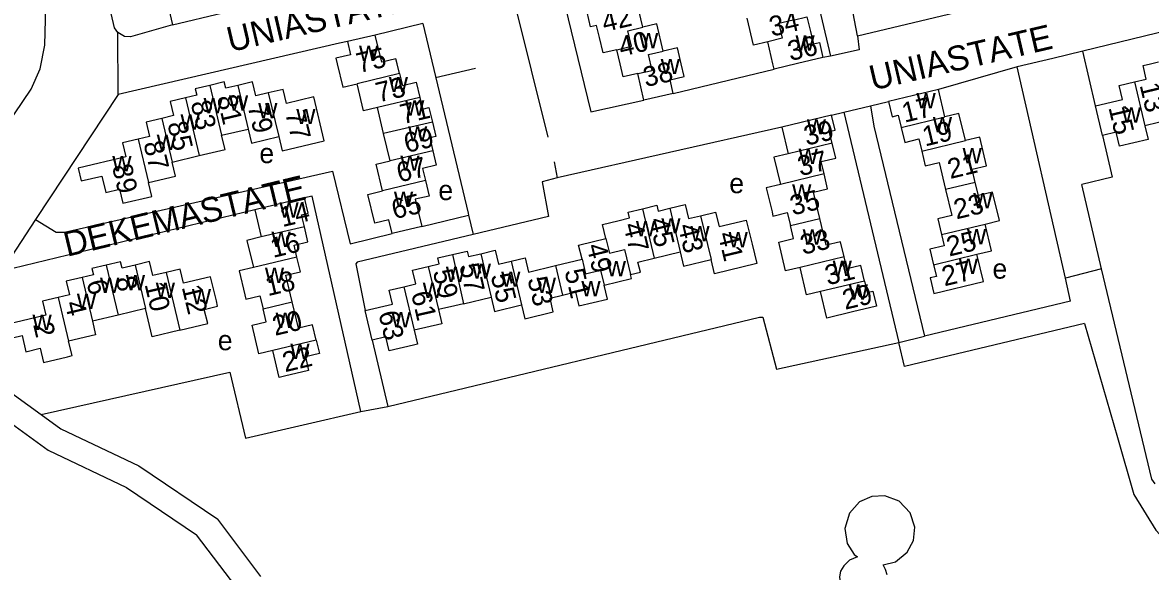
# Model space of a CAD drawing. Extents: x 157646 to 159241, y 379213 to 381217.
# Drawn here: x 158413 to 158640, y 380397.8 to 380508.3 of the extents above; entities that cross this region are included whole.
import ezdxf

# ---------------------------------------------------------------- set-up
doc = ezdxf.new("R2010")
doc.units = 0
for name, color, linetype in [('BLT_Basislijn', 7, 'Continuous'), ('BLT_Bebouwing', 7, 'Continuous'), ('BLT_Centroide', 7, 'Continuous'), ('BLT_Huisnummer', 7, 'Continuous'), ('BLT_Huisnummer_ tussenligend', 7, 'Continuous'), ('BLT_Onderverdeling_panden', 7, 'Continuous'), ('BLT_Straatnaam', 7, 'Continuous'), ('BLT_Vlakafsluiter', 7, 'Continuous')]:
    doc.layers.add(name, color=color, linetype=linetype)

msp = doc.modelspace()

# ---------------------------------------------------------------- linework, layer by layer
at = {"layer": 'BLT_Basislijn'}
for p, q in [((158581.07, 380505.63), (158578.69, 380518.3)), ((158493.56, 380508.08), (158483.99, 380505.77)), ((158626.43, 380502.53), (158620.37, 380501.06)), ((158629, 380491.49), (158626.43, 380502.53)), ((158575.65, 380501.55), (158574.12, 380501.22)), ((158620.37, 380501.06), (158613.19, 380499.36)), ((158504.16, 380499.04), (158496.14, 380497.15)), ((158543.97, 380494.03), (158564.31, 380498.87)), ((158613.19, 380499.36), (158597.35, 380494.78)), ((158622.92, 380456.82), (158613.19, 380499.36)), ((158578.33, 380490.24), (158583.67, 380491.51)), ((158583.67, 380491.51), (158587.29, 380492.37)), ((158575.86, 380489.66), (158578.33, 380490.24)), ((158578.33, 380490.24), (158589.42, 380443.84)), ((158565.83, 380487.25), (158520.61, 380477.03)), ((158519.99, 380480.22), (158520.61, 380477.03)), ((158630.17, 380458.72), (158626.25, 380475.68)), ((158459.75, 380470.6), (158408.83, 380458.22)), ((158415.6, 380468.65), (158408.83, 380458.22)), ((158493.33, 380467.25), (158502.78, 380469.5)), ((158502.78, 380469.5), (158503.69, 380465.58)), ((158630.17, 380458.72), (158622.92, 380456.82)), ((158623.96, 380452.17), (158594.59, 380445.15)), ((158483.39, 380444.35), (158486.52, 380431)), ((158589.42, 380443.84), (158594.59, 380445.15)), ((158407.74, 380435.87), (158416.7, 380429.36)), ((158481.1, 380429.98), (158486.52, 380431)), ((158460.93, 380396.74), (158452.27, 380408.29))]:
    msp.add_line(p, q, dxfattribs=at)
for points in [[(158382, 380486.03), (158394.7, 380478.15), (158397.65, 380476.58), (158401, 380475.76), (158402.65, 380477.1), (158414.74, 380494.85), (158416.53, 380498.98), (158417.47, 380503.76), (158417.68, 380511.48), (158409.95, 380583.17)], [(158432.15, 380506.31), (158431.46, 380507.21), (158430.83, 380510.09), (158424.78, 380563.88), (158424.7, 380564.63)], [(158581.93, 380543.49), (158581, 380543.28), (158567.24, 380539.99), (158567, 380538.29), (158575.65, 380501.55)], [(158504.69, 380526.29), (158505.57, 380522.37), (158518.89, 380525.34), (158527.39, 380490.29), (158538.07, 380492.65)], [(158581.07, 380505.63), (158618.83, 380514.67), (158619.9, 380514.93)], [(158691.66, 380491.57), (158680.6, 380511.16), (158678.79, 380513.56), (158677.11, 380514.16), (158675.83, 380514.19), (158665.87, 380512.12), (158626.43, 380502.53)], [(158505.34, 380511.18), (158511.1, 380512.31), (158512.05, 380512.19), (158518.7, 380485.21)], [(158443.18, 380507.82), (158434.73, 380505.44), (158433.52, 380505.48), (158432.15, 380506.31)], [(158493.56, 380508.08), (158502.68, 380469.93), (158502.78, 380469.5)], [(158478.38, 380504.44), (158476.81, 380504.14), (158432.24, 380493.79)], [(158581.07, 380505.63), (158581.39, 380502.81), (158575.65, 380501.55)], [(158432.24, 380493.79), (158415.6, 380468.65)], [(158583.67, 380491.51), (158584.39, 380487.45), (158594.59, 380445.15)], [(158630.41, 380485.56), (158632.37, 380477.18), (158626.25, 380475.68)], [(158415.6, 380468.65), (158419.74, 380466.05), (158421.43, 380466.05), (158475.39, 380478.34), (158478.91, 380463.75), (158487.39, 380465.84)], [(158520.61, 380477.03), (158517.59, 380476.23), (158518.87, 380469.24), (158503.69, 380465.58)], [(158481.1, 380429.98), (158471.3, 380473.31), (158469.72, 380472.97)], [(158503.69, 380465.58), (158480.37, 380460.04), (158480.05, 380459.72), (158481.98, 380450.28)], [(158623.96, 380452.17), (158622.92, 380456.82)], [(158640.99, 380415.42), (158640.35, 380416.32), (158630.17, 380458.72)], [(158486.52, 380431), (158561.35, 380448.95), (158562.04, 380449), (158564.77, 380438.53), (158589.42, 380443.84)], [(158626.79, 380447.71), (158590.56, 380439.04), (158589.42, 380443.84)], [(158626.79, 380447.71), (158633.39, 380424.75)], [(158416.7, 380429.36), (158454.68, 380437.9), (158457.86, 380424.59), (158481.1, 380429.98)], [(158404.8, 380431.83), (158418.11, 380422.16), (158433.89, 380414.67), (158447.97, 380405.16)], [(158416.7, 380429.36), (158420.67, 380426.47), (158436.38, 380419.03), (158452.27, 380408.29)], [(158633.39, 380424.75), (158636.69, 380413.23), (158641.14, 380406.08), (158645.36, 380401.49), (158645.92, 380400.19), (158645.87, 380396.15), (158642.14, 380389.54), (158637.32, 380383.71), (158629.31, 380376.48), (158618.08, 380369), (158616.64, 380365.53)], [(158583.93, 380412.89), (158581.5, 380411.8), (158579.44, 380409.53), (158578.52, 380406.45), (158579, 380403.42), (158580.43, 380401.17), (158581.04, 380400.73), (158579.43, 380400.03), (158578.3, 380398.92), (158577.65, 380397.83), (158577.43, 380396.71), (158577.57, 380395.45), (158577.86, 380394.21), (158578.56, 380393.09)], [(158587.05, 380397.1), (158586.71, 380398.18), (158586.27, 380399.12), (158588.72, 380399.7), (158591.1, 380401.63), (158592.34, 380404), (158592.6, 380406.66), (158591.67, 380409.57), (158589.46, 380411.91), (158586.6, 380413.01), (158583.93, 380412.89)], [(158371.84, 380404.74), (158408.18, 380378.92), (158409.65, 380377.6), (158411.02, 380375.86), (158413.89, 380370.53), (158415.7, 380360.95), (158417.2, 380357.34), (158418.61, 380354.92), (158421.49, 380351.01), (158424.52, 380348.6), (158429.22, 380345.84), (158436.86, 380344.43), (158443.38, 380345.1), (158477.93, 380359), (158481.57, 380360.73), (158481.57, 380361.05), (158447.97, 380405.16)]]:
    msp.add_lwpolyline(points, dxfattribs=at)
at = {"layer": 'BLT_Bebouwing'}
for p, q in [((158537.84, 380507.34), (158536.59, 380512.68)), ((158443.18, 380507.82), (158453.31, 380510.22)), ((158483.99, 380505.77), (158478.38, 380504.44)), ((158543.97, 380494.03), (158538.07, 380492.65)), ((158597.35, 380494.78), (158587.29, 380492.37)), ((158598.67, 380489.3), (158597.35, 380494.78)), ((158485.67, 380485.92), (158484.42, 380491.18)), ((158630.41, 380485.56), (158629, 380491.49)), ((158575.86, 380489.66), (158565.83, 380487.25)), ((158453.06, 380485.59), (158458.38, 380486.85)), ((158565.83, 380487.25), (158567.12, 380481.85)), ((158486.97, 380480.44), (158485.67, 380485.92)), ((158469.72, 380472.97), (158459.75, 380470.6)), ((158459.75, 380470.6), (158461.05, 380465.12)), ((158493.33, 380467.25), (158487.39, 380465.84)), ((158527.94, 380464.21), (158530.42, 380464.8)), ((158540.15, 380460.85), (158545.39, 380462.11)), ((158520.24, 380459.35), (158525.62, 380460.64)), ((158501.77, 380451.66), (158507.33, 380452.99)), ((158437.71, 380450.71), (158432.21, 380449.4)), ((158483.39, 380444.35), (158481.98, 380450.28)), ((158432.21, 380449.4), (158427.04, 380448.17))]:
    msp.add_line(p, q, dxfattribs=at)
for points in [[(158443.06, 380513.69), (158443.63, 380511.29), (158442.41, 380510.99), (158443.18, 380507.82)], [(158529.1, 380505.3), (158528.55, 380507.68), (158527.35, 380507.4), (158526.65, 380510.36)], [(158563, 380504.43), (158560.12, 380503.75), (158558.84, 380509.17)], [(158568.14, 380508.79), (158570.9, 380509.45), (158571.61, 380506.47)], [(158541.93, 380502.51), (158540.65, 380508), (158537.84, 380507.34)], [(158478.38, 380504.44), (158479, 380501.8), (158476.08, 380501.11), (158476.34, 380500), (158477.44, 380495.28), (158480.32, 380495.96)], [(158488.86, 380498.02), (158488.39, 380500), (158488.15, 380501.01), (158485.28, 380500.33), (158483.99, 380505.77)], [(158532.62, 380502.81), (158529.84, 380502.16), (158529.1, 380505.3)], [(158564.31, 380498.87), (158564.04, 380500), (158563, 380504.43)], [(158571.61, 380506.47), (158572.19, 380504.01), (158573.39, 380504.29), (158574.12, 380501.22)], [(158536.82, 380498), (158533.89, 380497.34), (158533.27, 380500), (158532.62, 380502.81)], [(158543.97, 380494.03), (158543.33, 380496.77), (158546.16, 380497.44), (158545.56, 380500), (158545.02, 380502.31), (158544.82, 380503.19), (158541.93, 380502.51)], [(158574.12, 380501.22), (158569.02, 380500.01), (158564.31, 380498.87)], [(158636.81, 380496.33), (158639.21, 380496.9), (158638.56, 380499.64), (158640.03, 380500), (158641.67, 380500.39)], [(158488.86, 380498.02), (158489.44, 380495.62), (158492.22, 380496.28), (158492.95, 380493.21)], [(158538.07, 380492.65), (158536.82, 380498)], [(158450.67, 380495.63), (158447.75, 380494.94), (158448.06, 380493.65), (158445.77, 380493.11)], [(158456.29, 380495.62), (158453.9, 380495.05), (158453.59, 380496.33), (158450.67, 380495.63)], [(158462.46, 380494.14), (158459.96, 380493.55), (158459.3, 380496.33), (158456.29, 380495.62)], [(158484.42, 380491.18), (158481.62, 380490.52), (158480.32, 380495.96)], [(158629, 380491.49), (158634.4, 380492.78), (158633.73, 380495.59), (158636.81, 380496.33)], [(158445.77, 380493.11), (158442.67, 380492.37), (158443.34, 380489.55), (158441.02, 380488.99)], [(158464.56, 380485.34), (158465.24, 380482.49), (158473.72, 380484.5), (158471.62, 380493.34), (158466.09, 380492.02), (158465.42, 380494.84), (158462.46, 380494.14)], [(158492.95, 380493.21), (158493.51, 380490.86), (158494.8, 380491.17), (158495.49, 380488.26)], [(158587.29, 380492.37), (158588.02, 380489.3), (158589.28, 380489.61), (158589.86, 380487.19)], [(158643.74, 380491.66), (158644.42, 380488.83), (158638.91, 380487.52)], [(158441.02, 380488.99), (158437.85, 380488.24), (158438.54, 380485.35), (158436.24, 380484.8)], [(158575.97, 380483.97), (158575.39, 380486.37), (158576.58, 380486.65), (158575.86, 380489.66)], [(158602.79, 380484.53), (158601.48, 380489.98), (158598.67, 380489.3)], [(158458.38, 380486.85), (158459.05, 380484.03), (158464.56, 380485.34)], [(158495.49, 380488.26), (158496.18, 380485.35), (158494.96, 380485.06), (158495.57, 380482.49)], [(158589.86, 380487.19), (158590.59, 380484.17), (158593.41, 380484.85), (158593.99, 380482.42)], [(158638.91, 380487.52), (158639.57, 380484.75), (158633.8, 380483.38), (158633.12, 380486.21), (158630.41, 380485.56)], [(158436.24, 380484.8), (158433.11, 380484.06), (158433.77, 380481.27), (158424.18, 380478.99), (158424.8, 380476.4), (158428.94, 380477.38), (158429.73, 380474.07), (158432.52, 380474.73), (158433.19, 380471.9), (158438.98, 380473.28), (158438.31, 380476.09)], [(158448.53, 380481.49), (158453.74, 380482.73), (158453.06, 380485.59)], [(158604.78, 380476.11), (158604.15, 380478.74), (158607.06, 380479.44), (158605.67, 380485.23), (158602.79, 380484.53)], [(158495.57, 380482.49), (158496.27, 380479.56), (158493.5, 380478.91), (158494.09, 380476.46)], [(158567.12, 380481.85), (158564.25, 380481.16), (158565.56, 380475.71)], [(158574.35, 380477.81), (158573.76, 380480.28), (158576.68, 380480.99), (158575.97, 380483.97)], [(158593.99, 380482.42), (158594.71, 380479.41), (158597.5, 380480.08), (158598.8, 380474.67)], [(158438.31, 380476.09), (158443.77, 380477.39), (158443.11, 380480.2)], [(158443.11, 380480.2), (158448.53, 380481.49)], [(158485.43, 380474.4), (158484.15, 380479.77), (158486.97, 380480.44)], [(158573.48, 380468.83), (158572.2, 380474.14), (158575.06, 380474.82), (158574.35, 380477.81)], [(158494.09, 380476.46), (158494.82, 380473.36), (158492.03, 380472.7), (158493.33, 380467.25)], [(158565.56, 380475.71), (158562.7, 380475.02), (158563.87, 380470.16), (158564.06, 380469.33), (158566.93, 380470.02), (158567.55, 380467.41)], [(158606.77, 380467.72), (158609.63, 380468.41), (158608.25, 380474.16), (158605.41, 380473.48), (158604.78, 380476.11)], [(158469.72, 380467.19), (158469.15, 380469.6), (158470.45, 380469.91), (158469.72, 380472.97)], [(158487.39, 380465.84), (158486.74, 380468.59), (158483.87, 380467.9), (158482.49, 380473.7), (158485.43, 380474.4)], [(158598.8, 380474.67), (158600.06, 380469.41), (158597.25, 380468.74), (158598, 380465.62)], [(158532.79, 380468.38), (158535.15, 380468.95), (158534.87, 380470.11), (158537.76, 380470.81)], [(158537.76, 380470.81), (158540.65, 380471.5), (158540.93, 380470.33), (158543.28, 380470.89)], [(158543.28, 380470.89), (158546.41, 380471.64), (158547.08, 380468.83), (158549.46, 380469.4)], [(158530.42, 380464.8), (158529.74, 380467.65), (158532.79, 380468.38)], [(158549.46, 380469.4), (158552.51, 380470.13), (158553.21, 380467.21), (158558.69, 380468.52), (158559.85, 380463.66), (158560.79, 380459.76), (158552.27, 380457.72), (158551.58, 380460.59)], [(158578.36, 380461.09), (158577.63, 380464.13), (158574.77, 380463.44), (158573.48, 380468.83)], [(158468.22, 380461.08), (158467.65, 380463.48), (158470.44, 380464.14), (158469.72, 380467.19)], [(158569.51, 380458.97), (158566.61, 380458.28), (158565.21, 380464.09), (158568.18, 380464.81), (158567.55, 380467.41)], [(158605.12, 380461.63), (158608.06, 380462.33), (158606.77, 380467.72)], [(158461.05, 380465.12), (158458.15, 380464.43), (158459.45, 380459)], [(158525.62, 380460.64), (158524.93, 380463.49), (158527.94, 380464.21)], [(158598, 380465.62), (158598.55, 380463.34), (158595.64, 380462.64), (158596.38, 380459.53)], [(158494.64, 380459.17), (158496.85, 380459.69), (158496.56, 380460.93), (158499.52, 380461.6)], [(158499.52, 380461.6), (158502.49, 380462.27), (158502.76, 380461.15), (158505.23, 380461.74)], [(158505.23, 380461.74), (158508.12, 380462.43), (158508.8, 380459.62), (158511.35, 380460.23)], [(158545.39, 380462.11), (158546.07, 380459.27), (158551.58, 380460.59)], [(158596.38, 380459.53), (158596.95, 380457.16), (158595.68, 380456.86), (158596.42, 380453.76), (158606.43, 380456.16), (158605.12, 380461.63)], [(158429.83, 380459.42), (158426.94, 380458.74), (158427.23, 380457.5), (158424.95, 380456.96)], [(158435.63, 380459.45), (158433.02, 380458.83), (158432.72, 380460.11), (158429.83, 380459.42)], [(158441.87, 380457.99), (158439.23, 380457.36), (158438.57, 380460.15), (158435.63, 380459.45)], [(158467.28, 380452.04), (158466.01, 380457.4), (158468.93, 380458.1), (158468.22, 380461.08)], [(158489.75, 380455.1), (158492.14, 380455.67), (158491.48, 380458.42), (158494.64, 380459.17)], [(158511.35, 380460.23), (158514.18, 380460.91), (158514.86, 380458.06), (158520.24, 380459.35)], [(158535.38, 380457.54), (158537.38, 380458.02), (158536.88, 380460.07), (158540.15, 380460.85)], [(158582.48, 380456.24), (158581.73, 380459.37), (158578.93, 380458.7), (158578.36, 380461.09)], [(158424.95, 380456.96), (158421.77, 380456.2), (158422.43, 380453.46), (158420.16, 380452.92)], [(158444.63, 380446.37), (158450.25, 380447.71), (158449.57, 380450.54), (158452.25, 380451.18), (158452, 380452.24), (158450.84, 380457.11), (158445.38, 380455.81), (158444.7, 380458.66), (158441.87, 380457.99)], [(158459.45, 380459), (158456.58, 380458.32), (158457.74, 380453.45), (158457.94, 380452.6), (158460.78, 380453.27), (158461.41, 380450.65)], [(158530.04, 380455.43), (158535.57, 380456.76), (158535.38, 380457.54)], [(158573.63, 380454.12), (158570.83, 380453.45), (158569.51, 380458.97)], [(158481.98, 380450.28), (158487.46, 380451.59), (158486.79, 380454.4), (158489.75, 380455.1)], [(158521.66, 380453.41), (158524.31, 380454.05), (158524.99, 380451.23), (158530.72, 380452.61), (158530.04, 380455.43)], [(158582.48, 380456.24), (158583.03, 380453.95), (158584.18, 380454.23), (158584.91, 380451.18), (158580.05, 380450.02), (158574.91, 380448.78), (158573.63, 380454.12)], [(158420.16, 380452.92), (158416.98, 380452.16), (158417.65, 380449.34), (158408.09, 380447.07), (158408.75, 380444.29), (158412.89, 380445.27), (158413.66, 380442.02), (158416.5, 380442.7), (158417.17, 380439.86), (158422.04, 380441.01), (158422.94, 380441.23), (158422.25, 380444.11)], [(158507.33, 380452.99), (158508.02, 380450.13), (158513.46, 380451.44)], [(158513.46, 380451.44), (158514.12, 380448.66), (158519.83, 380450.03), (158519.17, 380452.81), (158521.66, 380453.41)], [(158444.63, 380446.37), (158439.06, 380445.04), (158437.71, 380450.71)], [(158463.37, 380442.23), (158460.55, 380441.56), (158459.18, 380447.34), (158462.03, 380448.02), (158461.41, 380450.65)], [(158472.12, 380444.31), (158471.38, 380447.4), (158468.55, 380446.72), (158467.28, 380452.04)], [(158496.7, 380450.49), (158497.38, 380447.63), (158491.84, 380446.32)], [(158501.77, 380451.66), (158500, 380451.24), (158496.7, 380450.49)], [(158427.04, 380448.17), (158427.69, 380445.4), (158422.25, 380444.11)], [(158491.84, 380446.32), (158492.5, 380443.52), (158491.68, 380443.33), (158486.81, 380442.17), (158486.14, 380445), (158483.39, 380444.35)], [(158472.12, 380444.31), (158472.76, 380441.62), (158469.92, 380440.95), (158470.57, 380438.22), (158465.71, 380437.06), (158464.66, 380436.81), (158463.37, 380442.23)]]:
    msp.add_lwpolyline(points, dxfattribs=at)
at = {"layer": 'BLT_Onderverdeling_panden'}
for p, q in [((158488.86, 380498.02), (158480.32, 380495.96)), ((158450.67, 380495.63), (158453.06, 380485.59)), ((158456.29, 380495.62), (158458.38, 380486.85)), ((158636.81, 380496.33), (158638.91, 380487.52)), ((158445.77, 380493.11), (158448.53, 380481.49)), ((158462.46, 380494.14), (158464.56, 380485.34)), ((158492.95, 380493.21), (158484.42, 380491.18)), ((158441.02, 380488.99), (158443.11, 380480.2)), ((158589.86, 380487.19), (158598.67, 380489.3)), ((158495.49, 380488.26), (158485.67, 380485.92)), ((158436.24, 380484.8), (158438.31, 380476.09)), ((158593.99, 380482.42), (158602.79, 380484.53)), ((158495.57, 380482.49), (158486.97, 380480.44)), ((158575.97, 380483.97), (158567.12, 380481.85)), ((158574.35, 380477.81), (158565.56, 380475.71)), ((158494.09, 380476.46), (158485.43, 380474.4)), ((158604.78, 380476.11), (158598.8, 380474.67)), ((158537.76, 380470.81), (158540.15, 380460.85)), ((158543.28, 380470.89), (158545.39, 380462.11)), ((158549.46, 380469.4), (158551.58, 380460.59)), ((158567.55, 380467.41), (158573.48, 380468.83)), ((158469.72, 380467.19), (158461.05, 380465.12)), ((158598, 380465.62), (158606.77, 380467.72)), ((158499.52, 380461.6), (158501.77, 380451.66)), ((158505.23, 380461.74), (158507.33, 380452.99)), ((158596.38, 380459.53), (158605.12, 380461.63)), ((158429.83, 380459.42), (158432.21, 380449.4)), ((158435.63, 380459.45), (158437.71, 380450.71)), ((158468.22, 380461.08), (158459.45, 380459)), ((158494.64, 380459.17), (158496.7, 380450.49)), ((158511.35, 380460.23), (158513.46, 380451.44)), ((158520.24, 380459.35), (158521.66, 380453.41)), ((158578.36, 380461.09), (158569.51, 380458.97)), ((158424.95, 380456.96), (158427.04, 380448.17)), ((158441.87, 380457.99), (158444.63, 380446.37)), ((158489.75, 380455.1), (158491.84, 380446.32)), ((158582.48, 380456.24), (158573.63, 380454.12)), ((158420.16, 380452.92), (158422.25, 380444.11)), ((158461.41, 380450.65), (158467.28, 380452.04)), ((158472.12, 380444.31), (158463.37, 380442.23))]:
    msp.add_line(p, q, dxfattribs=at)
for points in [[(158532.62, 380502.81), (158535.59, 380503.51), (158534.86, 380506.65), (158537.84, 380507.34)], [(158568.14, 380508.79), (158565.22, 380508.1), (158565.92, 380505.12), (158563, 380504.43)], [(158536.82, 380498), (158539.74, 380498.66), (158539, 380501.83), (158541.93, 380502.51)], [(158530.42, 380464.8), (158531.13, 380461.83), (158534.18, 380462.56), (158535.38, 380457.54)], [(158525.62, 380460.64), (158526.33, 380457.68), (158529.33, 380458.4), (158530.04, 380455.43)]]:
    msp.add_lwpolyline(points, dxfattribs=at)
at = {"layer": 'BLT_Vlakafsluiter'}
msp.add_line((158432.24, 380493.79), (158432.15, 380506.31), dxfattribs=at)

# ---------------------------------------------------------------- texts
at = {"layer": 'BLT_Centroide'}
for s, p in [('w', (158537.09, 380503.13)), ('w', (158568.59, 380502.66)), ('w', (158480.73, 380500.53)), ('w', (158541.45, 380497.91)), ('w', (158486.71, 380494.28)), ('w', (158449.42, 380490.03)), ('w', (158454.53, 380490.56)), ('w', (158592.95, 380491)), ('w', (158460.42, 380489)), ('w', (158468.09, 380487.83)), ('w', (158489.99, 380489.56)), ('w', (158634.28, 380488.12)), ('w', (158444.78, 380486.73)), ('w', (158570.87, 380485.75)), ('w', (158596.24, 380486.19)), ('w', (158490.59, 380484.34)), ('w', (158440, 380482.62)), ('e', (158460.66, 380479.98)), ('w', (158569.22, 380479.84)), ('w', (158602.23, 380479.94)), ('w', (158431.05, 380478.34)), ('w', (158489.04, 380478.44)), ('e', (158496.69, 380472.54)), ('e', (158555.26, 380473.93)), ('w', (158567.92, 380472.62)), ('w', (158487.75, 380471.16)), ('w', (158604.38, 380470.88)), ('w', (158464.7, 380469.03)), ('w', (158536.47, 380465.23)), ('w', (158541.58, 380465.83)), ('w', (158463.1, 380463.09)), ('w', (158547.42, 380464.25)), ('w', (158555.12, 380463.03)), ('w', (158570.04, 380463.56)), ('w', (158603.12, 380463.62)), ('w', (158498.2, 380456.08)), ('w', (158503.42, 380456.69)), ('w', (158530.59, 380457.2)), ('w', (158576.07, 380457.28)), ('w', (158601.45, 380457.69)), ('e', (158608.25, 380456.72)), ('w', (158428.58, 380453.83)), ('w', (158433.77, 380454.39)), ('w', (158461.77, 380455.88)), ('w', (158509.34, 380455.09)), ('w', (158516.5, 380453.83)), ('w', (158439.8, 380452.86)), ('w', (158447.06, 380451.58)), ('w', (158493.56, 380452.81)), ('w', (158525.48, 380453.15)), ('w', (158579.3, 380452.5)), ('w', (158423.92, 380450.61)), ('w', (158487.23, 380446.91)), ('w', (158414.98, 380446.38)), ('w', (158463.92, 380446.81)), ('e', (158452.29, 380442.31)), ('w', (158466.89, 380440.56))]:
    msp.add_text(s, height=4, dxfattribs=at).set_placement(p)
at = {"layer": 'BLT_Huisnummer'}
for s, rotation, p in [('42', 13.1735, (158530.12, 380506.36)), ('36', 13.3226, (158567.55, 380500.52)), ('75', 13.3794, (158480.72, 380498.1)), ('38', 13.1739, (158538.43, 380495.27)), ('81', 283.366, (158452.06, 380493.26)), ('17', 13.4834, (158590.54, 380488.11)), ('15', 283.4016, (158631.57, 380491.19)), ('77', 283.3581, (158465.83, 380490.1)), ('39', 13.4809, (158570.81, 380483.47)), ('85', 283.3675, (158442.11, 380487.95)), ('69', 13.3714, (158490.28, 380482.01)), ('21', 13.4834, (158599.74, 380476.78)), ('89', 283.3715, (158430.97, 380479.34)), ('65', 13.3803, (158487.81, 380468.67)), ('14', 13.3766, (158465.3, 380467.09)), ('45', 283.4901, (158539.06, 380468.56)), ('41', 283.4905, (158552.92, 380465.72)), ('33', 13.4835, (158570.09, 380461.51)), ('49', 283.4957, (158526.49, 380463.34)), ('57', 282.7307, (158500.89, 380459.4)), ('27', 13.484, (158598.58, 380455.17)), ('18', 13.3714, (158462.37, 380453.18)), ('53', 283.4893, (158514.6, 380456.65)), ('6', 283.3702, (158425.83, 380456.06)), ('12', 283.3843, (158445.01, 380455.02)), ('29', 13.4894, (158578.57, 380450.44)), ('63', 283.3616, (158484.6, 380449.8)), ('2', 283.3782, (158415.09, 380447.49)), ('22', 13.3803, (158465.82, 380437.87))]:
    msp.add_text(s, height=4, rotation=rotation, dxfattribs=at).set_placement(p)
at = {"layer": 'BLT_Huisnummer_ tussenligend'}
for s, rotation, p in [('34', 13.3226, (158563.83, 380505.43)), ('40', 13.1739, (158533.52, 380501.4)), ('73', 13.3714, (158484.61, 380492.17)), ('13', 283.4015, (158637.85, 380495.7)), ('83', 283.366, (158446.8, 380492.15)), ('79', 283.3581, (158458.27, 380491.47)), ('71', 13.3714, (158489.52, 380487.8)), ('19', 13.4834, (158594.67, 380483.32)), ('87', 283.3675, (158437.29, 380484)), ('37', 13.4835, (158569.56, 380477.34)), ('67', 13.3803, (158488.82, 380476.07)), ('35', 13.4835, (158568.02, 380469.43)), ('23', 13.4834, (158600.98, 380468.64)), ('16', 13.3766, (158463.41, 380460.89)), ('47', 283.4901, (158533.89, 380467.54)), ('43', 283.4905, (158544.9, 380467.36)), ('25', 13.4834, (158599.53, 380461.16)), ('31', 13.4894, (158575.05, 380455.36)), ('8', 283.3702, (158431.68, 380456.74)), ('59', 282.7307, (158495.56, 380458.19)), ('55', 283.4893, (158507.2, 380457.34)), ('51', 283.4957, (158522.06, 380458.25)), ('10', 283.3702, (158437.52, 380455.59)), ('61', 282.7307, (158491.19, 380453.78)), ('4', 283.3782, (158421.45, 380451.8)), ('20', 13.3714, (158463.8, 380445.19))]:
    msp.add_text(s, height=4, rotation=rotation, dxfattribs=at).set_placement(p)
at = {"layer": 'BLT_Straatnaam'}
for s, rotation, p in [('UNIASTATE', 13.1222, (158454.77, 380502.31)), ('UNIASTATE', 13.1222, (158584.12, 380494.59)), ('DEKEMASTATE', 13.5361, (158421.94, 380461.11))]:
    msp.add_text(s, height=5, rotation=rotation, dxfattribs=at).set_placement(p)

doc.saveas('drawing.dxf')
